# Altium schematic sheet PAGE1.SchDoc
size 246 x 182 mm
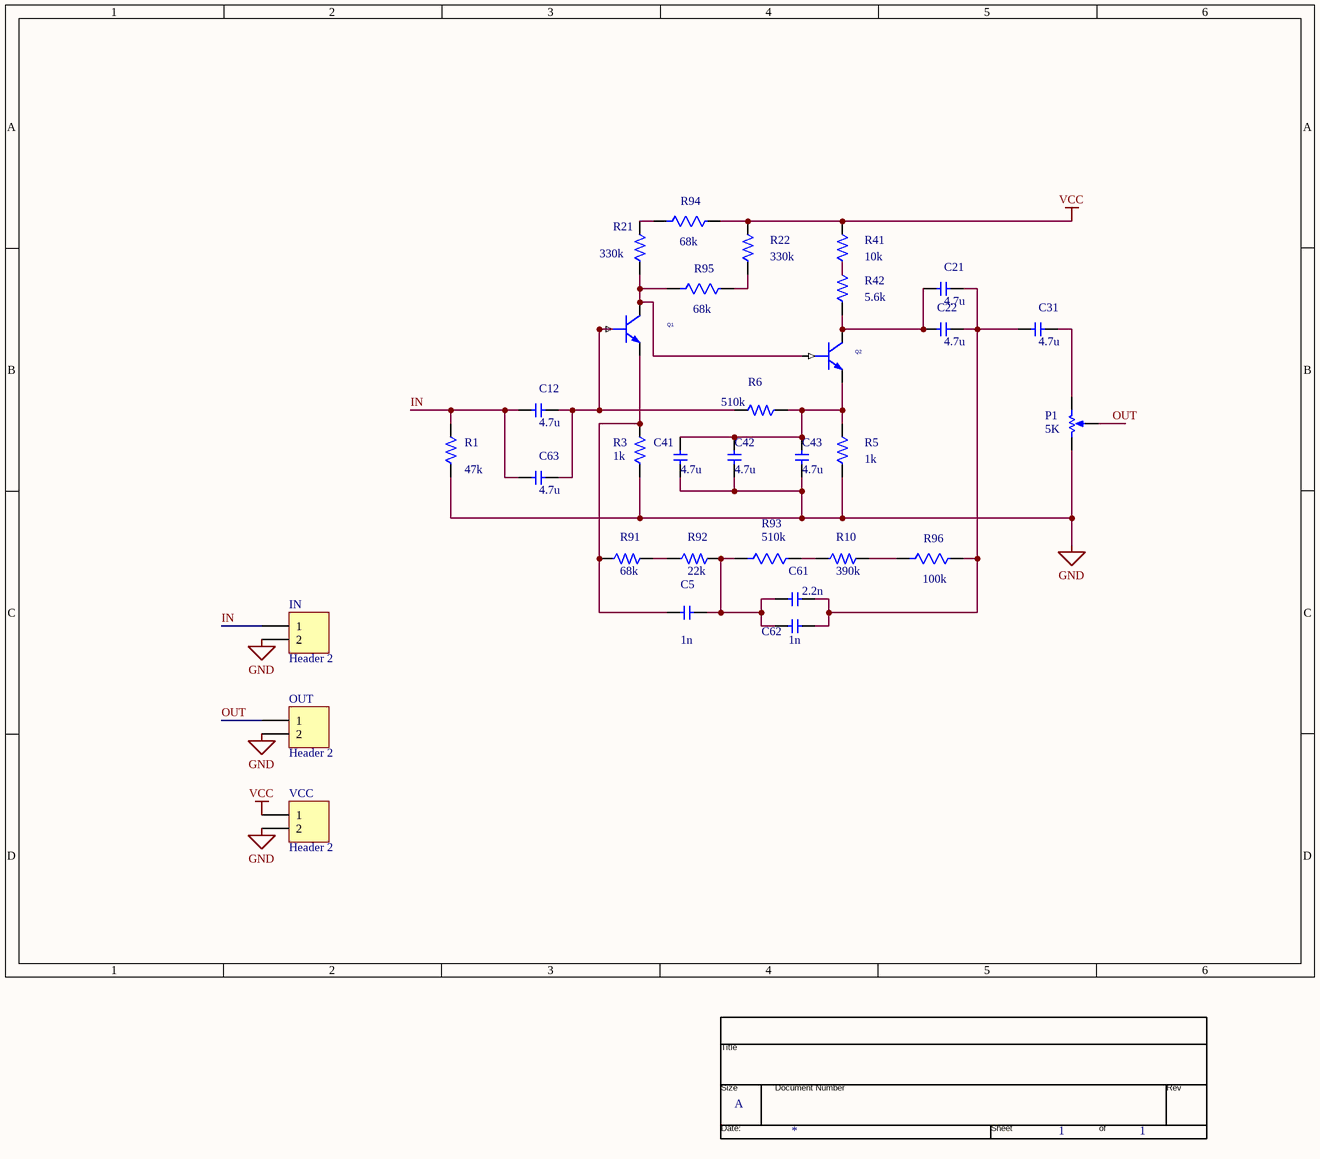
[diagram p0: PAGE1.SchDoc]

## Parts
*  Page Count: 1  Page Size: A  (hidden comment: TitleBlock0)  (graphical)
C5  1n  [C0805]
C12  4.7u  [C0805]
C21  4.7u  [C0805]
C22  4.7u  [C0805]
C31  4.7u  [C0805]
C41  4.7u  [C0805]
C42  4.7u  [C0805]
C43  4.7u  [C0805]
C61  2.2n  [C0805]
C62  1n  [C0805]
C63  4.7u  [C0805]
IN  Header 2  [C1210]
OUT  Header 2  [C1210]
P1  value 5K  [TS53YL104MR10]  (hidden comment: Potentiometer)
Q1  QBC846B  [SOT-23_N]  (value not drawn)
Q2  QBC846B  [SOT-23_N]  (value not drawn)
R1  47k  [6-0805_N]
R3  1k  [6-0805_N]
R5  1k  [6-0805_N]
R6  510k  [6-0805_N]
R10  390k  [6-0805_N]
R21  330k  [6-0805_N]
R22  330k  [6-0805_N]
R41  10k  [6-0805_N]
R42  5.6k  [6-0805_N]
R91  68k  [6-0805_N]
R92  22k  [6-0805_N]
R93  510k  [6-0805_N]
R94  68k  [6-0805_N]
R95  68k  [6-0805_N]
R96  100k  [6-0805_N]
VCC  Header 2  [C1210]

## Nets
GND: C41.1 C42.1 C43.1 IN.2 OUT.2 P1.2(BOT) R1.1 R3.1 R5.1 VCC.2
VCC: R22.2 R41.2 R94.2(B) VCC.1
IN: C12.1 C63.1 IN.1 R1.2
OUT: OUT.1 P1.3(TAP)
NetC5_1: C5.1 C61.2 C62.2 R92.2 R93.1(A)
NetC5_2: C5.2 Q1.1(E) R3.2 R91.1
NetC12_2: C12.2 C63.2 Q1.2(B) R6.2
NetC21_1: C21.1 C22.1 Q2.3(C) R42.1
NetC21_2: C21.2 C22.2 C31.1 C61.1 C62.1 R96.2(B)
NetC31_2: C31.2 P1.1(TOP)
NetC41_2: C41.2 C42.2 C43.2 Q2.1(E) R5.2 R6.1
NetQ1_3: Q1.3(C) Q2.2(B) R21.1 R95.1(A)
NetR10_1: R10.1 R93.2(B)
NetR10_2: R10.2 R96.1(A)
NetR21_2: R21.2 R94.1(A)
NetR22_1: R22.1 R95.2(B)
NetR41_1: R41.1 R42.2
NetR91_2: R91.2 R92.1

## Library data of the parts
C5 C12 C21 C22 C31 C41-C43 C61-C63 = C: VC2: 0; MAX_TEMP: CTMAX; SLOPE: CSMAX; KNEE: CBMAX; CURRENT: CIMAX; VOLTAGE: CMAX; PSpiceTemplate: C^@REFDES %1 %2 ?TOLERANCE¦C^@REFDES¦ @VALUE ?IC/IC=@IC/ TC=@TC1,@TC2 ?TOLERANCE¦\n.model C^@REFDES CAP C=1 DEV=@TOLERANCE% TC1=@TC1 TC2=@TC2 VC1=@VC1 VC2=@VC2¦; DIST: FLAT; PCB Footprint: cap196
IN OUT VCC = Header 2: Header, 2-Pin
P1 = Potentiometer: pin to pad: 1>A1 2>C1 3>B1; position: 0.5; SimulationGenericComponent: True
Q1 Q2 = QBC846B: pin to pad: 1>2 2>1; PSpiceTemplate: Q^@REFDES %C %B %E @MODEL ?AREA/@AREA/
R1 R10 R91 R92 = R: TC2: 0; POWER: RMAX; MAX_TEMP: RTMAX; SLOPE: RSMAX; VOLTAGE: RVMAX; PSpiceTemplate: R^@REFDES %1 %2 ?TOLERANCE¦R^@REFDES¦ @VALUE TC=@TC1,@TC2 ?TOLERANCE¦\n.model R^@REFDES RES R=1 DEV=@TOLERANCE% TC1=@TC1 TC2=@TC2¦; DIST: FLAT; BiasValue Power: 0W; PCB Footprint: AXRC05
R3 R5 R6 R21 R22 R41 R42 = R: TC2: 0; POWER: RMAX; MAX_TEMP: RTMAX; SLOPE: RSMAX; VOLTAGE: RVMAX; PSpiceTemplate: R^@REFDES %1 %2 ?TOLERANCE¦R^@REFDES¦ @VALUE TC=@TC1,@TC2 ?TOLERANCE¦\n.model R^@REFDES RES R=1 DEV=@TOLERANCE% TC1=@TC1 TC2=@TC2¦; DIST: FLAT; PCB Footprint: AXRC05
R93 R96 = RESISTOR: TC2: RTMPQ; TC1: RTMPL; MAX_TEMP: RTMAX; SLOPE: RSMAX; VOLTAGE: RVMAX; POWER: RMAX; DIST: FLAT; NEGTOL: RTOL%; TOL_ON_OFF: ON; BiasValue Power: 0W
R94 R95 = RESISTOR: TC2: RTMPQ; TC1: RTMPL; MAX_TEMP: RTMAX; SLOPE: RSMAX; VOLTAGE: RVMAX; POWER: RMAX; DIST: FLAT; NEGTOL: RTOL%; TOL_ON_OFF: ON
